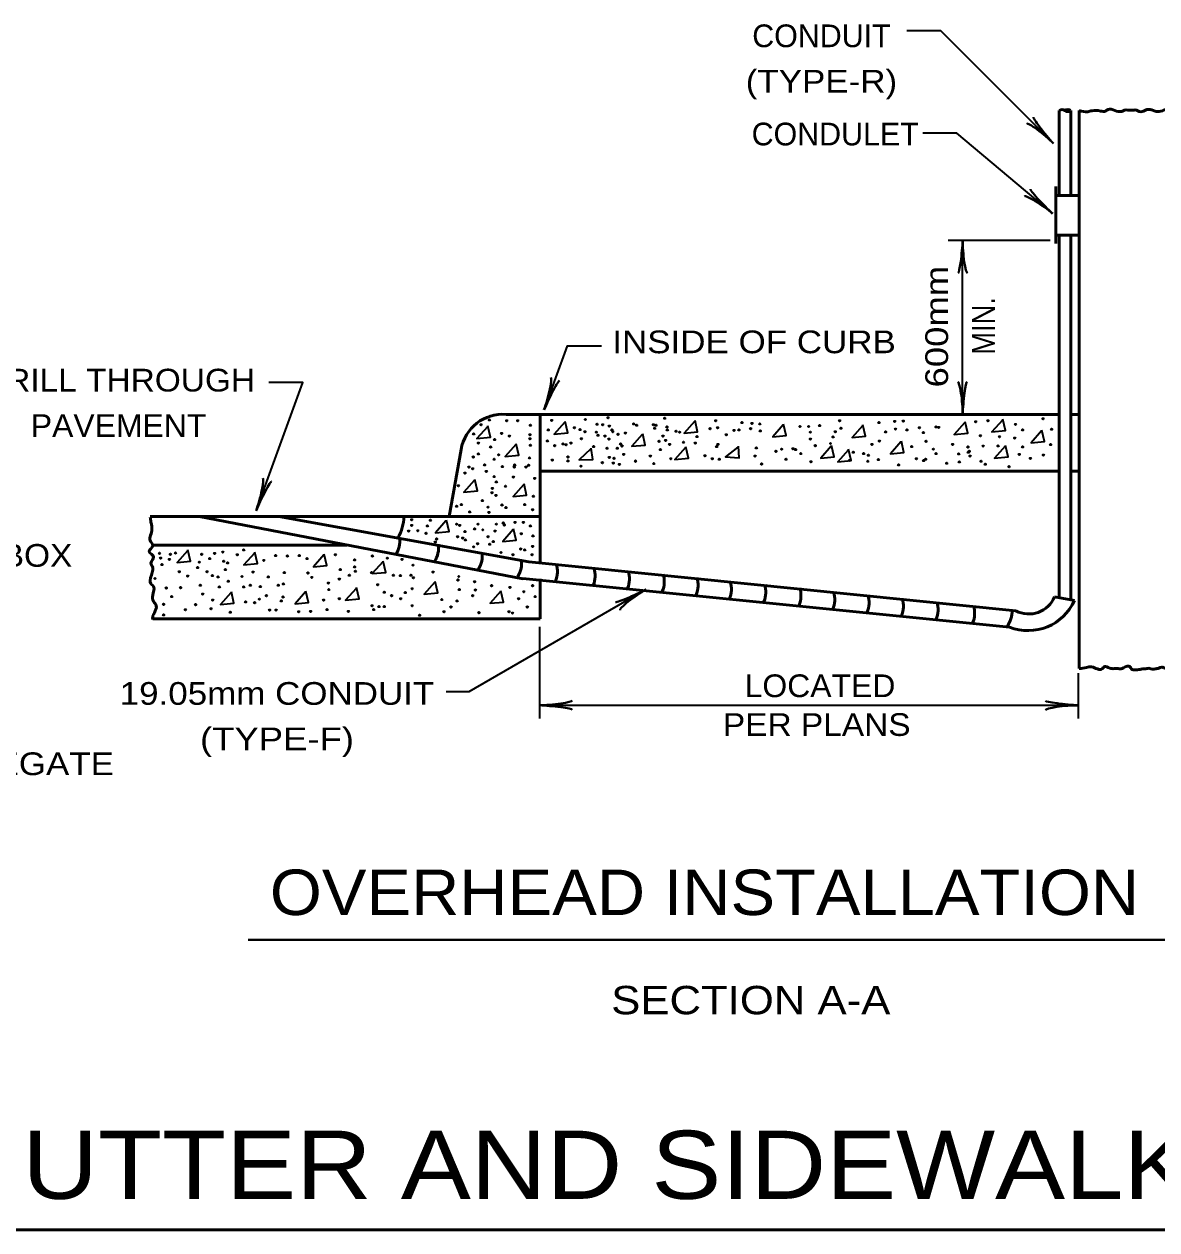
# Model space of a CAD drawing. Extents: x -90 to 623, y -379 to 75.
# Drawn here: x 108.4 to 208.1, y -115.6 to -9.5 of the extents above; entities that cross this region are included whole.
import ezdxf
from ezdxf.enums import TextEntityAlignment as Align

# ---------------------------------------------------------------- set-up
doc = ezdxf.new("R2010")
doc.units = 0
doc.header["$LTSCALE"] = 0.8
doc.layers.add('1', color=7, linetype='Continuous', lineweight=35)

msp = doc.modelspace()

# ---------------------------------------------------------------- linework, layer by layer
at = {"layer": '1', "lineweight": 53}
for p, q in [((199.5023, -24.5454), (199.5023, -17.0762)), ((200.5023, -24.5244), (200.5023, -17.0762)), ((201.2523, -66.201), (201.2523, -17.0762)), ((199.1939, -23.7608), (199.1939, -28.7608)), ((199.2202, -24.5454), (199.5083, -24.5454)), ((199.5083, -24.5454), (201.2523, -24.5454)), ((199.5023, -59.9576), (199.5023, -28.0425)), ((200.5023, -60.1339), (200.5023, -28.0425)), ((199.5023, -43.8166), (150.8137, -43.8166)), ((153.8137, -43.8166), (153.8137, -56.8222)), ((201.2523, -43.8166), (200.5175, -43.8166)), ((145.8137, -52.8166), (146.8556, -46.9078)), ((199.5023, -48.8166), (153.8137, -48.8166)), ((201.2523, -48.8166), (200.5175, -48.8166)), ((153.8137, -52.8166), (119.4935, -52.8166)), ((123.8137, -52.8166), (152.2946, -58.2973)), ((130.8137, -52.8166), (152.8137, -56.8038)), ((119.7456, -55.3166), (136.805, -55.3166)), ((152.8137, -56.8038), (195.6844, -61.108)), ((152.2983, -58.2597), (195.115, -62.5583)), ((153.8137, -58.2809), (153.8137, -61.8166)), ((199.0793, -59.883), (200.8487, -60.195)), ((153.8137, -61.8166), (119.7177, -61.8166)), ((0.8544, -115.6087), (216.8702, -115.6087))]:
    msp.add_line(p, q, dxfattribs=at)
at = {"layer": '1'}
for p, q in [((198.7092, -28.4962), (189.7092, -28.4962)), ((190.9945, -43.8166), (190.9945, -28.4962)), ((153.7517, -62.5142), (153.7517, -70.593)), ((201.167, -66.593), (201.167, -70.593)), ((153.7517, -69.4262), (201.1672, -69.4262))]:
    msp.add_line(p, q, dxfattribs=at)
at = {"layer": '1', "lineweight": 40}
msp.add_line((128.1151, -90.0752), (209.7699, -90.0752), dxfattribs=at)
at = {"layer": '1'}
for points in [[(198.9823, -19.9613), (189.0828, -10.0618), (186.0828, -10.0618)], [(198.9141, -26.1397), (190.4876, -19.069), (187.4876, -19.069)], [(154.1624, -43.4171), (156.2145, -37.7789), (159.2145, -37.7789)], [(128.8216, -52.2943), (132.9258, -41.018), (129.9258, -41.018)], [(155.9672, -44.5178), (155.0458, -45.5543), (156.2358, -45.4392), (156.0055, -44.4411)], [(167.4068, -44.4411), (166.4855, -45.4776), (167.6755, -45.3624), (167.4452, -44.3643)], [(191.169, -44.5562), (190.2477, -45.5927), (191.4377, -45.4776), (191.2073, -44.4795)], [(194.4926, -44.3167), (193.5712, -45.3532), (194.7612, -45.238), (194.5309, -44.2399)], [(149.1725, -44.9017), (148.2512, -45.9382), (149.4412, -45.8231), (149.2108, -44.825)], [(162.8003, -45.5927), (161.8789, -46.6292), (163.0689, -46.5141), (162.8386, -45.516)], [(175.1996, -44.7482), (174.2782, -45.7847), (175.4682, -45.6695), (175.2379, -44.6714)], [(182.1863, -44.8249), (181.2649, -45.8614), (182.4549, -45.7462), (182.2246, -44.7482)], [(197.9359, -45.2748), (197.0146, -46.3113), (198.2046, -46.1962), (197.9742, -45.1981)], [(151.6677, -46.4756), (150.7463, -47.5121), (151.9363, -47.3969), (151.706, -46.3988)], [(166.6007, -46.7443), (165.6793, -47.7808), (166.8693, -47.6657), (166.639, -46.6676)], [(171.2086, -46.6964), (170.1213, -47.5572), (171.3132, -47.6504), (171.2596, -46.6275)], [(179.4222, -46.6292), (178.5009, -47.6657), (179.6909, -47.5505), (179.4606, -46.5524)], [(185.5643, -46.2453), (184.643, -47.2818), (185.833, -47.1667), (185.6027, -46.1686)], [(194.7322, -46.6223), (193.8108, -47.6587), (195.0008, -47.5436), (194.7705, -46.5455)], [(158.2607, -46.8574), (157.2525, -47.8097), (158.448, -47.7987), (158.3055, -46.7843)], [(180.9244, -46.9531), (180.0031, -47.9896), (181.1931, -47.8744), (180.9627, -46.8763)], [(148.0208, -49.6234), (147.0995, -50.6599), (148.2895, -50.5448), (148.0592, -49.5467)], [(152.3587, -50.0073), (151.4373, -51.0438), (152.6273, -50.9287), (152.397, -49.9306)], [(145.5256, -53.1935), (144.6043, -54.23), (145.7943, -54.1148), (145.5639, -53.1167)], [(151.4373, -53.9613), (150.516, -54.9978), (151.706, -54.8827), (151.4757, -53.8846)], [(122.7816, -55.818), (121.8602, -56.8545), (123.0502, -56.7393), (122.8199, -55.7413)], [(128.6732, -56.0343), (127.7519, -57.0707), (128.9419, -56.9556), (128.7116, -55.9575)], [(134.7769, -56.1878), (133.8556, -57.2243), (135.0456, -57.1092), (134.8152, -56.1111)], [(139.9593, -56.802), (139.038, -57.8385), (140.228, -57.7233), (139.9977, -56.7252)], [(133.1647, -59.4508), (132.2433, -60.4873), (133.4333, -60.3722), (133.203, -59.3741)], [(137.6177, -59.1437), (136.6963, -60.1802), (137.8863, -60.065), (137.656, -59.0669)], [(144.5275, -58.6062), (143.6062, -59.6427), (144.7962, -59.5276), (144.5658, -58.5295)], [(163.1207, -59.2342), (147.5323, -68.2342), (145.5323, -68.2342)], [(150.3241, -59.4124), (149.4027, -60.4489), (150.5927, -60.3337), (150.3624, -59.3357)], [(126.6003, -59.5276), (125.6789, -60.5641), (126.8689, -60.4489), (126.6386, -59.4508)]]:
    msp.add_lwpolyline(points, dxfattribs=at)
at = {"layer": '1', "lineweight": 53}
msp.add_lwpolyline([(199.2202, -28.0454), (200.4964, -28.0454), (201.2523, -28.0454)], dxfattribs=at)
at = {"layer": '1'}
for centre in [(149.3453, -44.3063), (150.8808, -44.3831), (151.8406, -44.3831), (154.8348, -44.3447), (157.7907, -44.2679), (159.7869, -44.1143), (164.7774, -44.1527), (169.2688, -44.3831), (171.5721, -44.5367), (172.455, -44.6134), (180.171, -44.3831), (183.6259, -44.5367), (185.015, -44.4354), (185.7635, -44.4054), (192.1481, -44.4598), (193.219, -44.3755), (198.0696, -44.1958), (147.9633, -45.5347), (148.6159, -44.7286), (150.4202, -45.4963), (152.9154, -45.6115), (152.9538, -44.767), (154.5277, -45.1893), (156.831, -44.9973), (157.3301, -45.1508), (157.7524, -45.3427), (158.7505, -45.3812), (158.8272, -44.6902), (158.904, -45.6499), (159.3262, -44.7286), (159.9021, -44.8438), (160.1324, -45.1893), (160.2092, -45.3427), (160.6698, -45.5731), (161.3225, -45.4579), (162.0518, -44.6518), (162.3206, -44.767), (163.7793, -44.7286), (163.8945, -45.0357), (164.0097, -44.767), (164.9693, -44.9205), (165.0077, -45.1893), (165.7755, -45.3044), (166.0826, -45.3812), (168.7697, -45.0741), (169.4223, -44.9973), (170.1901, -45.6115), (170.8811, -45.2276), (171.3033, -45.1893), (172.3398, -45.0741), (173.146, -44.6518), (173.1844, -45.266), (176.6777, -44.8822), (177.4455, -44.8822), (177.599, -45.3812), (178.4052, -44.8053), (179.7872, -45.3427), (180.2862, -45.0357), (184.2066, -45.3636), (185.0847, -45.1125), (186.0929, -45.1839), (187.196, -44.9973), (187.5415, -45.4196), (188.6548, -44.9205), (188.8851, -44.9589), (192.5602, -45.6929), (195.6442, -44.7048), (196.2731, -45.1839), (198.8181, -45.1241), (148.3857, -46.3409), (149.4605, -46.6864), (149.806, -46.0338), (151.1112, -45.7267), (152.9154, -45.957), (152.9538, -46.5328), (154.4509, -46.149), (155.1035, -46.5712), (155.8329, -46.4177), (156.1017, -46.4944), (156.5239, -46.3409), (157.4452, -45.957), (158.5202, -46.648), (159.5182, -45.7267), (159.8637, -45.9954), (160.9002, -46.4177), (161.0153, -46.6096), (164.2783, -46.1873), (164.6238, -45.7267), (164.8542, -46.1106), (165.1997, -46.4561), (166.4281, -46.2641), (167.4646, -46.3409), (167.6181, -45.7651), (169.3456, -46.648), (169.4607, -46.4561), (172.8389, -46.7632), (177.599, -45.9954), (178.0212, -46.5712), (179.3648, -46.3792), (179.5952, -45.8034), (183.0118, -46.4561), (183.6676, -46.172), (186.5121, -46.6511), (187.7718, -46.1873), (190.1135, -46.4561), (191.4571, -46.6863), (192.8007, -46.6096), (194.1172, -46.5912), (194.237, -45.7828), (195.5844, -45.9025), (196.2731, -46.681), (198.7283, -46.4714), (147.925, -47.5693), (148.3857, -47.3006), (149.7676, -47.7612), (150.1515, -47.3774), (152.877, -47.6461), (156.2552, -47.5693), (159.7102, -46.8015), (159.9021, -47.6077), (160.3244, -47.6845), (160.5931, -46.8015), (161.1689, -47.339), (163.5106, -47.4925), (164.3935, -46.9167), (165.3148, -47.7228), (168.3091, -47.4542), (168.9617, -47.7228), (169.5759, -47.7612), (172.7237, -47.4925), (174.5663, -47.0703), (175.0654, -46.8783), (175.4493, -47.7612), (176.0635, -46.8399), (176.2938, -46.9167), (176.7545, -47.2622), (181.3611, -47.147), (182.2823, -47.2622), (182.7047, -47.4157), (183.5876, -47.7996), (186.9273, -47.7228), (187.7335, -47.7612), (188.4245, -46.8783), (188.6548, -47.2622), (190.651, -47.3006), (191.4955, -47.147), (191.5722, -47.0703), (191.6491, -47.4925), (195.9737, -47.3397), (196.9617, -47.699), (198.0995, -47.3996), (147.5411, -48.4522), (147.8866, -48.6058), (148.9231, -48.2603), (149.0766, -48.8362), (150.497, -48.4138), (151.5334, -48.4522), (151.5718, -48.2603), (152.5699, -48.4522), (152.8003, -48.2987), (154.8732, -47.838), (156.2552, -47.9148), (157.4068, -48.3755), (159.2879, -48.0683), (160.2476, -48.1067), (160.785, -48.2219), (162.2054, -47.9147), (162.2054, -47.9532), (163.8177, -48.1451), (173.2996, -48.1835), (177.6374, -47.9916), (181.0156, -47.8764), (182.6496, -47.9386), (185.3534, -48.2602), (187.56, -47.8787), (189.5961, -48.1182), (190.7039, -47.9984), (192.6202, -47.9386), (192.9795, -48.2081), (195.0754, -48.4177), (147.1956, -48.9897), (149.7676, -49.2967), (149.9595, -49.7574), (151.4567, -49.3352), (153.3377, -49.4503), (146.6197, -50.1029), (149.5757, -50.7172), (149.6141, -50.3332), (149.9212, -50.9475), (150.7657, -50.1413), (146.4663, -51.9072), (146.8885, -51.7536), (148.7311, -51.4082), (149.2302, -51.9839), (150.4586, -51.792), (150.8041, -52.0223), (152.4547, -51.7536), (153.2225, -51.0242), (142.5122, -53.0972), (147.6178, -52.4062), (149.3069, -52.4446), (153.1457, -52.2142), (142.2435, -54.0953), (142.5122, -53.5962), (143.0497, -54.0569), (143.8942, -53.6347), (144.1629, -53.1356), (146.4663, -53.4811), (146.7349, -53.5962), (147.1956, -54.1337), (148.0402, -53.9033), (148.3473, -53.4811), (148.7695, -53.9802), (149.8443, -54.0953), (149.9595, -53.4811), (150.5737, -53.3659), (150.6505, -53.5578), (151.6103, -53.3275), (152.3396, -53.3275), (152.9538, -53.6347), (143.7791, -54.2873), (144.5852, -55.055), (144.7003, -54.7862), (146.543, -54.5943), (147.0037, -54.7095), (147.234, -54.8631), (148.3088, -55.2086), (149.2302, -54.5943), (149.3837, -55.2469), (149.6908, -55.0166), (152.1477, -54.3257), (153.1842, -54.5176), (120.3167, -56.0487), (121.2747, -56.1385), (121.7239, -56.0187), (124.0292, -56.1385), (125.1608, -56.0532), (125.8902, -55.938), (127.157, -56.1683), (127.7328, -55.746), (130.5352, -56.2451), (131.5717, -56.2835), (132.6082, -56.2451), (135.7943, -56.1683), (139.0573, -56.2835), (147.9633, -55.4772), (150.3818, -55.9763), (151.4183, -56.1683), (152.1093, -55.6692), (152.4547, -55.746), (153.1073, -56.1683), (153.1457, -55.4389), (120.4066, -56.4678), (120.5263, -57.0367), (121.185, -56.5876), (123.6699, -57.3061), (123.8197, -56.8271), (124.7386, -56.5138), (125.967, -56.7442), (126.3125, -56.8977), (129.4987, -56.6673), (133.2992, -56.5138), (137.4834, -56.629), (137.4834, -57.2432), (140.3625, -56.4754), (141.6677, -56.5906), (142.6274, -57.0896), (119.9275, -58.2642), (122.0532, -57.6654), (122.8017, -58.0546), (124.5082, -57.6654), (124.9689, -58.0109), (125.4679, -58.1261), (126.1206, -57.4735), (127.5793, -58.0877), (128.5501, -57.6953), (129.8826, -58.1261), (131.3029, -57.7422), (133.3759, -57.7806), (133.7214, -58.1645), (136.1398, -58.3181), (136.2166, -57.4735), (137.0228, -57.9726), (137.5602, -57.6271), (138.9806, -57.7422), (140.9, -57.9726), (141.5142, -58.0109), (142.4355, -57.9726), (142.6658, -58.2029), (144.3932, -57.7038), (146.5814, -58.3948), (146.6582, -58.0877), (120.9155, -59.1025), (122.173, -59.0726), (123.9095, -58.863), (125.5831, -59.009), (126.3645, -58.5037), (127.7328, -59.009), (128.3087, -58.8555), (129.1916, -58.9707), (130.7655, -58.8555), (131.2262, -58.7403), (135.1802, -58.6635), (135.2185, -59.2393), (139.518, -58.8171), (140.0938, -59.4697), (142.5507, -59.1626), (146.6966, -59.2393), (148.0402, -58.5483), (148.1169, -59.2777), (149.5373, -58.8938), (151.1496, -59.0474), (152.378, -59.4313), (153.1457, -58.8938), (120.676, -60.5396), (121.3946, -59.851), (124.1191, -59.6414), (125.0073, -60.1607), (127.8914, -60.33), (128.6926, -60.391), (129.1148, -60.0839), (129.729, -59.7767), (131.0342, -60.2374), (131.1877, -59.8919), (134.7578, -60.1607), (136.1398, -60.0455), (140.7464, -59.7767), (141.5526, -60.0455), (141.9364, -59.5081), (145.1611, -60.1223), (146.5047, -60.2374), (147.8866, -59.7767), (151.9173, -60.0455), (153.3761, -59.8536), (120.676, -61.4677), (122.5922, -61.0186), (123.4903, -60.5695), (124.8537, -60.9284), (126.5428, -61.2355), (129.9977, -61.0436), (130.5736, -61.0436), (132.5697, -61.1972), (133.6062, -61.1587), (135.065, -61.0052), (136.946, -61.1587), (139.0189, -60.6597), (139.1725, -61.0052), (139.6332, -60.7365), (140.0938, -60.7365), (142.5507, -60.6597), (143.2032, -61.5042), (145.353, -61.1972), (145.9672, -60.7749), (148.424, -61.2739), (151.0728, -61.1972), (151.3799, -61.3123), (152.6851, -60.7749)]:
    msp.add_circle(centre, 0.0607, dxfattribs=at)
at = {"layer": '1', "lineweight": 53}
for centre, radius, start, end in [((199.7498, -17.3906), 0.4001, 51.28288, 128.19904), ((200.2502, -17.3906), 0.4001, 51.80096, 128.71712), ((200.2502, -16.7662), 0.4001, 231.28288, 308.19904), ((150.5255, -47.5272), 3.7218, 85.55938, 170.41856), ((138.0774, -52.8064), 3.7363, 329.7014, 359.8431), ((139.2853, -54.9951), 2.1707, 327.00343, 7.84739), ((142.7018, -55.5709), 2.1707, 327.00343, 7.84739), ((146.5544, -56.2619), 2.1707, 327.00343, 7.84739), ((150.0185, -56.8976), 2.1707, 327.00343, 7.84739), ((153.1665, -57.6512), 2.1707, 337.00343, 17.84739), ((156.4868, -58.0188), 2.1707, 337.00343, 17.84739), ((159.508, -58.2831), 2.1707, 337.00343, 17.84739), ((162.5673, -58.5508), 2.1707, 337.00343, 17.84739), ((165.5468, -58.85), 2.1707, 337.00343, 17.84739), ((168.4814, -59.2224), 2.1707, 337.00343, 17.84739), ((171.5059, -59.4484), 2.1707, 337.00343, 17.84739), ((174.6001, -59.7577), 2.1707, 337.00343, 17.84739), ((177.5729, -60.1334), 2.1707, 337.00343, 17.84739), ((180.5941, -60.3977), 2.1707, 337.00343, 17.84739), ((183.6119, -60.7003), 2.1707, 337.00343, 17.84739), ((186.6679, -61.0061), 2.1707, 337.00343, 17.84739), ((196.7237, -58.3241), 4.5295, 249.19696, 335.60393), ((196.8228, -58.946), 2.4434, 242.23273, 337.44956), ((189.8769, -61.3254), 2.1707, 337.00343, 17.84739), ((193.1718, -61.1685), 2.1707, 322.00343, 2.84739)]:
    msp.add_arc(centre, radius, start, end, dxfattribs=at)
at = {"layer": '1', "lineweight": 40}
for centre, major_axis, ratio, start_param, end_param in [((198.3396, -19.0194), (1.1178, -1.3662), 0.07063, 3.14071475, 5.41810995), ((198.0154, -19.3851), (1.3731, -1.1523), 0.122415, 0.89635335, 3.14159265), ((198.1917, -25.2573), (1.2326, -1.2636), 0.07063, 3.14071475, 5.41810995), ((197.9006, -25.6499), (1.4683, -1.0282), 0.122415, 0.89635335, 3.14159265), ((190.7829, -29.6168), (-0.1757, -1.7565), 0.07063, 6.28230741, 8.55970261), ((190.7829, -29.6168), (-0.1757, -1.7565), 0.07063, 6.28230741, 8.55970261), ((191.2708, -29.5874), (-0.1562, 1.7857), 0.122415, 0.89635335, 3.14159265), ((191.2708, -29.5874), (-0.1562, 1.7857), 0.122415, 0.89635335, 3.14159265), ((154.276, -42.2972), (-0.464, -1.7314), 0.122415, 0.89635335, 3.14159265), ((154.276, -42.2972), (-0.464, -1.7314), 0.122415, 0.89635335, 3.14159265), ((154.7445, -42.4365), (0.7658, 1.5905), 0.07063, 6.28230741, 8.55970261), ((154.7445, -42.4365), (0.7658, 1.5905), 0.07063, 6.28230741, 8.55970261), ((190.7182, -42.7254), (0.1562, -1.7857), 0.122415, 0.89635335, 3.14159265), ((190.7182, -42.7254), (0.1562, -1.7857), 0.122415, 0.89635335, 3.14159265), ((191.2061, -42.6961), (0.1757, 1.7565), 0.07063, 6.28230741, 8.55970261), ((191.2061, -42.6961), (0.1757, 1.7565), 0.07063, 6.28230741, 8.55970261), ((128.9352, -51.1744), (-0.464, -1.7314), 0.122415, 0.89635335, 3.14159265), ((128.9352, -51.1744), (-0.464, -1.7314), 0.122415, 0.89635335, 3.14159265), ((129.4037, -51.3138), (0.7658, 1.5904), 0.07063, 6.28230741, 8.55970261), ((129.4037, -51.3138), (0.7658, 1.5904), 0.07063, 6.28230741, 8.55970261), ((162.0446, -59.6112), (1.609, 0.7261), 0.07063, 3.14071475, 5.41810995), ((162.0446, -59.6112), (1.609, 0.7261), 0.07063, 3.14071475, 5.41810995), ((162.3139, -60.0191), (1.4684, 1.0281), 0.122415, 0.89635335, 3.14159265), ((162.3139, -60.0191), (1.4684, 1.0281), 0.122415, 0.89635335, 3.14159265), ((154.8429, -69.1499), (-1.7857, -0.1562), 0.122415, 0.89635335, 3.14159265), ((154.8723, -69.6378), (1.7565, -0.1757), 0.07063, 6.28230741, 8.55970261), ((200.076, -69.7025), (1.7857, 0.1562), 0.122415, 0.89635335, 3.14159265), ((200.0467, -69.2146), (1.7565, -0.1757), 0.07063, 3.14071475, 5.41810995)]:
    msp.add_ellipse(centre, major_axis=major_axis, ratio=ratio, start_param=start_param, end_param=end_param, dxfattribs=at)
at = {"layer": '1', "lineweight": 53}
for points in [[(201.2523, -17.0762), (202.0042, -17.1688), (202.3784, -17.079), (203.1119, -17.1089), (203.576, -17.1089), (203.7856, -16.9742), (204.3844, -17.064), (204.9982, -17.1389), (205.2378, -17.0341), (205.8515, -17.0491), (206.2856, -17.0341), (206.5401, -17.1538), (207.0342, -17.064), (207.1389, -17.0042), (207.4982, -16.9742), (207.6778, -17.0191), (208.0222, -17.1389), (208.5761, -17.079), (208.7558, -17.0191), (209.0551, -17.0341), (209.2523, -17.0762)], [(119.5024, -52.8765), (119.5642, -53.2926), (119.6409, -54.0603), (119.4873, -54.5977), (119.4873, -54.9048), (119.7177, -55.3655), (119.4106, -55.9029), (119.7944, -56.3636), (119.5642, -56.901), (119.7177, -57.2848), (119.7177, -57.5152), (119.4873, -58.4365), (119.4873, -58.5901), (119.7944, -58.9739), (119.7177, -59.7417), (119.7944, -60.2791), (120.0247, -60.663), (119.8712, -61.2772), (119.7177, -61.6611), (119.7177, -61.8765)], [(201.2523, -66.201), (201.8918, -66.0967), (202.3409, -66.0517), (203.2841, -66.2164), (203.4638, -66.0218), (203.9427, -66.1566), (204.332, -66.2015), (204.6912, -66.2015), (205.0356, -66.2015), (205.1553, -66.1267), (205.7392, -66.0517), (205.859, -66.2464), (206.1583, -66.2913), (206.6075, -66.2763), (206.8919, -66.2164), (207.0267, -66.2164), (207.371, -66.1715), (207.7602, -66.2464), (208.1045, -66.1865), (208.2692, -66.1566), (208.5087, -66.0817), (208.7632, -66.1416), (209.0177, -66.2314), (209.2523, -66.201)]]:
    msp.add_spline(points, degree=3, dxfattribs=at)

# ---------------------------------------------------------------- texts
at = {"layer": '1'}
msp.add_text('CONDUIT', height=2, dxfattribs=at).set_placement((178.5693, -11.4893), align=Align.CENTER)
for s, width, p in [('(TYPE-R)', 1.15, (178.5693, -15.4893)), ('DRILL THROUGH', 1.1, (116.7143, -41.8023)), ('PAVEMENT', 1.05, (116.7143, -45.8023)), ('JUNCTION BOX', 1.1, (101.6947, -57.2317)), ('19.05mm CONDUIT', 1.15, (130.6558, -69.3843)), ('(TYPE-F)', 1.2, (130.6558, -73.3843))]:
    msp.add_text(s, height=2, dxfattribs=dict(at, width=width)).set_placement(p, align=Align.CENTER)
msp.add_text('CONDULET', height=2, dxfattribs=at).set_placement((172.4247, -20.1359))
for s, width, p in [('600mm', 1.2, (189.7084, -41.4451)), ('MIN.', 0.9, (193.828, -38.5653))]:
    msp.add_text(s, height=2, rotation=90, dxfattribs=dict(at, width=width)).set_placement(p)
for s, height, width, p in [('INSIDE OF CURB', 2, 1.15, (160.1649, -38.4319)), ('LOCATED', 2, 1.05, (171.8098, -68.7078)), ('PER PLANS', 2, 1.1, (169.8982, -72.1213)), ('300mm AGGREGATE', 2, 1.15, (85.7188, -75.5731)), ('OVERHEAD INSTALLATION', 4, 1.1, (130.0267, -87.8905)), ('SECTION A-A', 2.5, 1.15, (160.0668, -96.6295)), ('TYPICAL SECTION IN GUTTER AND SIDEWALK', 6, 1.15, (4.6777, -112.8777))]:
    msp.add_text(s, height=height, dxfattribs=dict(at, width=width)).set_placement(p)

doc.saveas('drawing.dxf')
